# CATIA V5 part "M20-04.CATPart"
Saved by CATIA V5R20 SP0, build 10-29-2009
Part number: M20-04
Revision: ANY
Definition: UNKNOWN
Nomenclature: M20-04
Source: Unknown
Bounding box of the stored display mesh (mm): x -41 to 41, y -41 to 41, z 0 to 8
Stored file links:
  C:\Users\Utente\Desktop\IO LAVORO\3D X SITO CF\X 3D SITO CF 27-09-2020\740T\740T-20\M20-04.CATPart
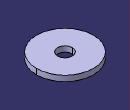
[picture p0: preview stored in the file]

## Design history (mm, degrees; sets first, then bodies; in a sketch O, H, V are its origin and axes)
Body1 "NONE" (main body)
  Solid1: solid without history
